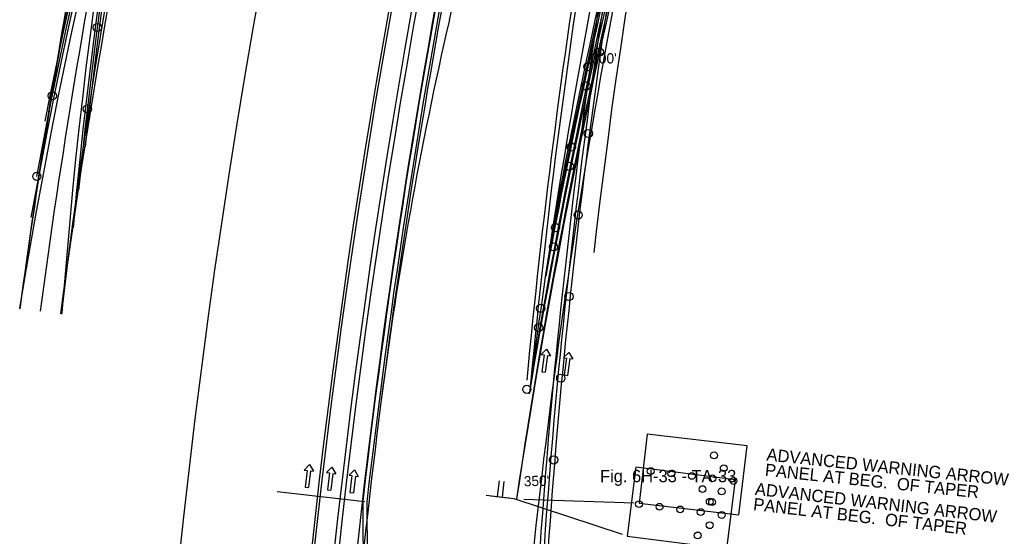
# Model space of a CAD drawing. Extents: x 659657 to 668193, y 633084 to 648639.
# Drawn here: x 661299.5 to 661782, y 640412.7 to 640664.4 of the extents above; entities that cross this region are included whole.
import ezdxf

# ---------------------------------------------------------------- set-up
doc = ezdxf.new("R2010")
doc.units = 0
for name, color, linetype in [('R_Border Prem', 7, 'Continuous'), ('R_MOT_Stage 1A', 7, 'Continuous'), ('R_MOT_Stage 1A_Striping', 7, 'Continuous'), ('R_MOT_Stage 1B', 7, 'Continuous'), ('R_MOT_Stage 1B_Striping', 7, 'Continuous'), ('R_MOT_Stage 1C', 7, 'Continuous'), ('R_MOT_Stage 1C_Striping', 7, 'Continuous'), ('R_MOT_Stage 2', 7, 'Continuous'), ('R_MOT_Stage 2_Striping', 7, 'Continuous'), ('R_MOT_Stage 2_Striping_PPM', 7, 'Continuous'), ('R_MOT_Stage 3', 7, 'Continuous'), ('R_MOT_Stage 3_Striping', 7, 'Continuous'), ('R_MOT_Stage 3_Striping_PPM', 7, 'Continuous'), ('R_MOT_Stage 4_Striping_PPM', 7, 'Continuous'), ('R_MOT_Stage 5_Striping_PPM', 7, 'Continuous'), ('T_SIGNAL CONTROL CABINET', 7, 'Continuous'), ('TEMP_DETECTION ZONE_Stage 2', 7, 'Continuous'), ('TEMP_SIGNAL_HEAD_STAGE 2', 7, 'Continuous')]:
    doc.layers.add(name, color=color, linetype=linetype)

msp = doc.modelspace()

# ---------------------------------------------------------------- linework, layer by layer
at = {"layer": 'R_Border Prem'}
msp.add_arc((665219.85, 639999.01), 3863.72, 156.12343, 201.98495, dxfattribs=at)
at = {"layer": 'R_MOT_Stage 1A'}
for centre in [(661576.6, 640641.57), (661568.42, 640602.4), (661560.73, 640563.13), (661553.5, 640523.77), (661546.76, 640484.34)]:
    msp.add_circle(centre, 2, dxfattribs=at)
for radius, start, end in [(3295.92, 166.52246, 170.60391), (3297.92, 166.521, 169.55029)]:
    msp.add_arc((664800.12, 639948.5), radius, start, end, dxfattribs=at)
at = {"layer": 'R_MOT_Stage 1A_Striping'}
msp.add_arc((664800.12, 639948.5), 3293.92, 166.52393, 171.57983, dxfattribs=at)
at = {"layer": 'R_MOT_Stage 1B'}
for centre in [(661582.09, 640648.67), (661576.73, 640609.02), (661571.82, 640569.32), (661567.35, 640529.57), (661563.32, 640489.76), (661559.84, 640449.93)]:
    msp.add_circle(centre, 2, dxfattribs=at)
for centre, radius, start, end in [((665125.14, 640149.59), 3594.47, 170.86744, 174.58577), ((665125.5, 640149.65), 3579.83, 170.87569, 174.59402), ((665125.5, 640149.65), 3577.83, 170.87671, 174.59402), ((665193.55, 640152.91), 3647.29, 174.74563, 179.20276), ((665193.55, 640152.91), 3645.29, 174.74563, 178.47875)]:
    msp.add_arc(centre, radius, start, end, dxfattribs=at)
at = {"layer": 'R_MOT_Stage 1B_Striping'}
for centre, radius, start, end in [((665125.14, 640149.59), 3592.47, 170.86744, 174.58577), ((665125.5, 640149.65), 3581.83, 170.87569, 174.59402), ((665193.55, 640152.91), 3649.29, 174.74563, 179.29562)]:
    msp.add_arc(centre, radius, start, end, dxfattribs=at)
at = {"layer": 'R_MOT_Stage 1C'}
for centre in [(661575.68, 640632.19), (661567.49, 640593.02), (661559.79, 640553.76), (661552.56, 640514.41)]:
    msp.add_circle(centre, 2, dxfattribs=at)
for centre, radius, start, end in [((665219.85, 639999.01), 3777.72, 163.39403, 173.45222), ((665219.85, 639999.01), 3775.72, 163.39403, 173.45222), ((664764.51, 639945.28), 3261.1, 166.32277, 170.52352), ((664764.51, 639945.28), 3263.1, 166.32343, 169.50902), ((665254.05, 640442.69), 3787.3, 180.1951, 182.8995), ((665254.61, 640442.99), 3785.88, 180.20324, 182.90425)]:
    msp.add_arc(centre, radius, start, end, dxfattribs=at)
at = {"layer": 'R_MOT_Stage 1C_Striping'}
for centre, radius, start, end in [((665219.85, 639999.01), 3799.97, 157.70222, 174.95222), ((665219.85, 639999.01), 3788.97, 157.70222, 174.95222), ((665219.85, 639999.01), 3777.97, 163.39302, 174.95222), ((664764.51, 639945.28), 3259.1, 166.3221, 171.43192)]:
    msp.add_arc(centre, radius, start, end, dxfattribs=at)
at = {"layer": 'R_MOT_Stage 2'}
for points in [[(661305.15, 640568.04), (661308.17, 640584.41), (661310.92, 640598.98), (661313.76, 640613.75), (661316.65, 640628.56), (661319.67, 640643.38), (661322.82, 640658.15), (661326.02, 640672.87), (661329.23, 640687.29), (661332.6, 640702.01), (661336.07, 640716.66), (661337.14, 640721.22)], [(661311.96, 640614.98), (661314.69, 640628.95), (661317.71, 640643.79), (661320.86, 640658.57), (661324.07, 640673.3), (661327.28, 640687.73), (661330.65, 640702.47), (661334.12, 640717.12), (661335.19, 640721.64)]]:
    msp.add_lwpolyline(points, dxfattribs=at)
for centre in [(661315.41, 640627.39), (661307.85, 640588.11)]:
    msp.add_circle(centre, 2, dxfattribs=at)
at = {"layer": 'R_MOT_Stage 2_Striping'}
for points in [[(661299.53, 640523.59), (661299.7, 640524.68), (661302.18, 640539.53), (661304.74, 640554.4), (661307.41, 640569.23), (661310.13, 640584.04), (661312.88, 640598.6), (661315.72, 640613.37), (661318.61, 640628.17), (661321.63, 640642.97), (661324.77, 640657.73), (661327.97, 640672.44), (661331.18, 640686.85), (661334.55, 640701.56), (661338.01, 640716.2), (661339.1, 640720.8)], [(661319.98, 640521.04), (661320.05, 640521.64), (661321.8, 640536.55), (661323.65, 640551.45), (661325.59, 640566.33), (661327.59, 640581.21), (661329.64, 640595.84), (661331.76, 640610.7), (661333.93, 640625.55), (661336.22, 640640.39), (661338.64, 640655.21), (661341.13, 640670.01), (661343.63, 640684.5), (661346.27, 640699.28), (661349.03, 640714.03), (661349.89, 640718.68)]]:
    msp.add_lwpolyline(points, dxfattribs=at)
at = {"layer": 'R_MOT_Stage 2_Striping_PPM'}
msp.add_line((661508.98, 640664.33), (661547.98, 640833.29), dxfattribs=at)
for centre, radius, start, end in [((665219.85, 639999.01), 3798.72, 158.32294, 176.45222), ((665219.85, 639999.01), 3786.72, 158.32294, 176.45222), ((665219.85, 639999.01), 3774.72, 165.19143, 172.71234), ((664866.31, 640052.27), 3335.18, 168.52205, 177.48815), ((664865.6, 640051.85), 3345.49, 168.51431, 172.49699), ((663362.62, 640236.52), 1902.36, 167.00403, 172.71236), ((665219.85, 639999.01), 3774.72, 172.71235, 176.45222)]:
    msp.add_arc(centre, radius, start, end, dxfattribs=at)
at = {"layer": 'R_MOT_Stage 3'}
msp.add_lwpolyline([(661345.94, 640728.2), (661343.98, 640715.05), (661341.78, 640700.27), (661339.71, 640685.48), (661337.6, 640670.36), (661335.67, 640655.55), (661333.77, 640640.75), (661332.03, 640625.93), (661330.3, 640611.11), (661328.76, 640596.28), (661327.21, 640581.19), (661325.58, 640563.03)], dxfattribs=at)
for centre in [(661337.35, 640660.69), (661332.46, 640620.99)]:
    msp.add_circle(centre, 2, dxfattribs=at)
at = {"layer": 'R_MOT_Stage 3_Striping'}
msp.add_lwpolyline([(661343.96, 640728.49), (661342, 640715.34), (661339.8, 640700.56), (661337.73, 640685.75), (661335.62, 640670.63), (661333.69, 640655.8), (661331.78, 640640.99), (661330.04, 640626.16), (661328.31, 640611.33), (661326.77, 640596.49), (661325.22, 640581.38), (661323.89, 640566.51), (661322.56, 640551.6), (661321.31, 640536.69), (661320.06, 640521.76), (661320.04, 640521.47)], dxfattribs=at)
msp.add_arc((664934.73, 640031.5), 3668.36, 169.14567, 172.29086, dxfattribs=at)
at = {"layer": 'R_MOT_Stage 3_Striping_PPM'}
msp.add_line((661508.98, 640664.33), (661547.98, 640833.29), dxfattribs=at)
for centre, radius, start, end in [((665219.85, 639999.01), 3798.72, 158.32294, 176.45222), ((665219.85, 639999.01), 3786.72, 158.32294, 176.45222), ((665219.85, 639999.01), 3774.72, 165.19143, 172.71234), ((664866.31, 640052.27), 3335.18, 168.52205, 177.48815), ((664865.6, 640051.85), 3345.49, 168.51431, 172.49699), ((663362.62, 640236.52), 1902.36, 167.00403, 172.71236), ((665219.85, 639999.01), 3774.72, 172.71235, 176.45222)]:
    msp.add_arc(centre, radius, start, end, dxfattribs=at)
at = {"layer": 'R_MOT_Stage 4_Striping_PPM'}
msp.add_line((661508.98, 640664.33), (661547.98, 640833.29), dxfattribs=at)
for centre, radius, start, end in [((665219.85, 639999.01), 3798.72, 158.32294, 176.45222), ((665219.85, 639999.01), 3786.72, 158.32294, 176.45222), ((665219.85, 639999.01), 3774.72, 165.19143, 172.71234), ((664936.08, 640039.23), 3648.67, 167.27675, 172.4107), ((664936.08, 640039.23), 3668.67, 168.84564, 172.41325), ((664936.08, 640039.23), 3658.67, 168.84564, 172.41198), ((664866.31, 640052.27), 3335.18, 168.52205, 177.48815), ((664865.6, 640051.85), 3345.49, 168.51431, 172.49699), ((663362.62, 640236.52), 1902.36, 167.00403, 172.71236), ((665219.85, 639999.01), 3774.72, 172.71235, 176.45222)]:
    msp.add_arc(centre, radius, start, end, dxfattribs=at)
at = {"layer": 'R_MOT_Stage 5_Striping_PPM'}
msp.add_line((661508.98, 640664.33), (661547.98, 640833.29), dxfattribs=at)
for centre, radius, start, end in [((665219.85, 639999.01), 3798.72, 158.32294, 176.45222), ((665219.85, 639999.01), 3786.72, 158.32294, 176.45222), ((665219.85, 639999.01), 3774.72, 165.19143, 172.71234), ((664936.08, 640039.23), 3648.67, 167.27675, 172.4107), ((664936.08, 640039.23), 3668.67, 168.84564, 172.41325), ((664936.08, 640039.23), 3658.67, 168.84564, 172.41198), ((664866.31, 640052.27), 3335.18, 168.52205, 177.48815), ((664865.6, 640051.85), 3345.49, 168.51431, 172.49699), ((663362.62, 640236.52), 1902.36, 167.00403, 172.71236), ((665219.85, 639999.01), 3774.72, 172.71235, 176.45222)]:
    msp.add_arc(centre, radius, start, end, dxfattribs=at)
at = {"layer": 'T_SIGNAL CONTROL CABINET'}
for p, q in [((661553.79, 640501.31), (661556.42, 640503.88)), ((661553.79, 640501.31), (661555.18, 640501.11)), ((661555.18, 640501.11), (661554.02, 640492.92)), ((661556.42, 640503.88), (661558.24, 640500.68)), ((661564.68, 640499.76), (661567.32, 640502.34)), ((661567.32, 640502.34), (661569.13, 640499.13)), ((661556.85, 640500.87), (661555.69, 640492.68)), ((661556.85, 640500.87), (661558.24, 640500.68)), ((661564.68, 640499.76), (661566.07, 640499.57)), ((661566.07, 640499.57), (661564.91, 640491.37)), ((661567.74, 640499.33), (661566.58, 640491.14)), ((661567.74, 640499.33), (661569.13, 640499.13)), ((661554.02, 640492.92), (661555.69, 640492.68)), ((661564.91, 640491.37), (661566.58, 640491.14)), ((661438.23, 640445), (661440.81, 640447.64)), ((661438.23, 640445), (661439.63, 640444.84)), ((661439.63, 640444.84), (661438.67, 640436.62)), ((661441.31, 640444.64), (661440.34, 640436.42)), ((661440.81, 640447.64), (661442.7, 640444.48)), ((661441.31, 640444.64), (661442.7, 640444.48)), ((661449.16, 640443.72), (661451.73, 640446.36)), ((661449.16, 640443.72), (661450.55, 640443.56)), ((661450.55, 640443.56), (661449.59, 640435.34)), ((661452.23, 640443.36), (661451.27, 640435.14)), ((661451.73, 640446.36), (661453.63, 640443.2)), ((661452.23, 640443.36), (661453.63, 640443.2)), ((661460.08, 640442.44), (661462.66, 640445.08)), ((661462.66, 640445.08), (661464.55, 640441.92)), ((661460.08, 640442.44), (661461.48, 640442.28)), ((661461.48, 640442.28), (661460.52, 640434.06)), ((661463.16, 640442.08), (661462.19, 640433.86)), ((661463.16, 640442.08), (661464.55, 640441.92)), ((661425.05, 640434.58), (661467.77, 640429.68)), ((661438.67, 640436.62), (661440.34, 640436.42)), ((661449.59, 640435.34), (661451.27, 640435.14)), ((661460.52, 640434.06), (661462.19, 640433.86))]:
    msp.add_line(p, q, dxfattribs=at)
for points in [[(661579.65, 640551.04), (661580.8, 640561.32), (661582.55, 640576.19), (661584.47, 640591.04), (661586.35, 640605.92), (661588.2, 640620.77), (661590.39, 640635.57), (661592.59, 640650.4), (661594.77, 640665.23), (661596.98, 640679.61), (661599.3, 640694.41), (661601.68, 640709.2), (661604.08, 640724), (661606.52, 640738.78), (661608.97, 640753.57), (661610.53, 640762.96)], [(661346.93, 640728.06), (661344.97, 640714.9), (661342.77, 640700.13), (661340.7, 640685.34), (661338.59, 640670.23), (661336.67, 640655.42), (661334.76, 640640.62), (661333.02, 640625.81), (661331.3, 640611), (661329.75, 640596.18), (661328.23, 640581.38)], [(661347.92, 640727.92), (661345.96, 640714.76), (661343.76, 640699.99), (661341.69, 640685.2), (661339.58, 640670.09), (661337.66, 640655.29), (661335.75, 640640.5), (661334.01, 640625.7), (661332.29, 640610.9), (661331.41, 640602.44)], [(661307.85, 640588.11), (661309.94, 640599.17), (661312.78, 640613.95), (661315.67, 640628.75), (661318.69, 640643.58), (661321.84, 640658.36), (661325.04, 640673.09), (661328.25, 640687.51), (661331.63, 640702.24), (661335.09, 640716.89), (661336.17, 640721.43)]]:
    msp.add_lwpolyline(points, dxfattribs=at)
msp.add_arc((664781.19, 639959.47), 3277.87, 165.78448, 169.38222, dxfattribs=at)
at = {"layer": 'TEMP_DETECTION ZONE_Stage 2'}
for p, q in [((661532.48, 640432.09), (661533.46, 640439.7)), ((661538.01, 640431.21), (661526.86, 640432.64)), ((661540.51, 640431.1), (661593.28, 640413.76))]:
    msp.add_line(p, q, dxfattribs=at)
msp.add_lwpolyline([(661648.58, 640440.17), (661599.99, 640446.4), (661595.67, 640412.78), (661644.27, 640406.55)], close=True, dxfattribs=at)
for centre in [(661632.44, 640435.68), (661601.48, 640428.35), (661611.5, 640427.07), (661637.12, 640429.39), (661621.53, 640425.78), (661631.55, 640424.49), (661641.8, 640423.1), (661635.94, 640418.1), (661630.09, 640413.1)]:
    msp.add_circle(centre, 1.66, dxfattribs=at)
at = {"layer": 'TEMP_SIGNAL_HEAD_STAGE 2'}
for p, q in [((661534.83, 640431.81), (661535.73, 640439.44)), ((661540.37, 640431), (661529.2, 640432.31)), ((661545.37, 640430.82), (661599.05, 640428.94))]:
    msp.add_line(p, q, dxfattribs=at)
msp.add_lwpolyline([(661654.16, 640456.8), (661605.5, 640462.51), (661601.54, 640428.85), (661650.21, 640423.14)], close=True, dxfattribs=at)
for centre in [(661638.06, 640452.14), (661607.18, 640444.48), (661617.22, 640443.3), (661627.26, 640442.12), (661642.81, 640445.9), (661637.3, 640440.94), (661647.55, 640439.66), (661641.76, 640434.6), (661635.96, 640429.54)]:
    msp.add_circle(centre, 1.66, dxfattribs=at)

# ---------------------------------------------------------------- texts
at = {"layer": 'T_SIGNAL CONTROL CABINET'}
for s, height, p in [("300'", 5, (661578.16, 640643.14)), ('Fig. 6H-33 - TA-33', 6, (661582.47, 640439.06))]:
    msp.add_text(s, height=height, dxfattribs=at).set_placement(p)
msp.add_text("350'", height=5, rotation=1.6349, dxfattribs=at).set_placement((661545.36, 640437.02))
at = {"layer": 'TEMP_DETECTION ZONE_Stage 2'}
for s, p in [('ADVANCED WARNING ARROW', (661657.81, 640432.94)), ('PANEL AT BEG.  OF TAPER', (661656.94, 640425.48))]:
    msp.add_text(s, height=6, rotation=353.3814, dxfattribs=at).set_placement(p)
at = {"layer": 'TEMP_SIGNAL_HEAD_STAGE 2'}
for s, p in [('ADVANCED WARNING ARROW', (661663.46, 640449.67)), ('PANEL AT BEG.  OF TAPER', (661662.68, 640442.2))]:
    msp.add_text(s, height=6, rotation=353.9948, dxfattribs=at).set_placement(p)

doc.saveas('drawing.dxf')
